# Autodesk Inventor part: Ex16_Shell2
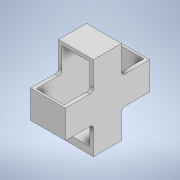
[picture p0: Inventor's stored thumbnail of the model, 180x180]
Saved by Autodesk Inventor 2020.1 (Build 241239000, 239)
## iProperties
Created: 2019-10
Part Number: Ex16_Shell2
Material: Generic
Document SubType Name: Modeling
Designer: Synergysoft Dell02
Density: 1 g/cm^3
Appearance: Default
Author: Synergysoft Dell02
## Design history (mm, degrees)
sketch "Sketch1"
  geometry: L1 (20, 60)-(-20, 60); L2 (-20, 60)-(-20, -60); L3 (-20, -60)-(20, -60); L4 (20, -60)-(20, 60); L5 (20, 60)-(-20, -60); L6 (-20, 60)-(20, -60); L7 (-60, -20)-(60, -20); L8 (60, -20)-(60, 20); L9 (60, 20)-(-60, 20); L10 (-60, 20)-(-60, -20); L11 (-60, -20)-(60, 20); L12 (60, -20)-(-60, 20); 5 further points
  constraints: 24 end point, 4 midpoint, 4 parallel, 2 horizontal, 2 perpendicular
  dimensions: "d0" = 40 distance of L3.end L2.end; "d1" = 120 distance of L2.end L1.end; "d2" = 120 distance of L9.end L8.end; "d3" = 40 distance of L8.end L7.end
extrude "Extrusion1" new body sketch "Sketch1" stored distance "d4" = 50; taper "d5" = 0 deg
fillet "Fillet1" dims "d6" = 5
shell "Shell1" dims "d7" = 5, "d8" = 3, "d9" = 10
body "Solid1"
